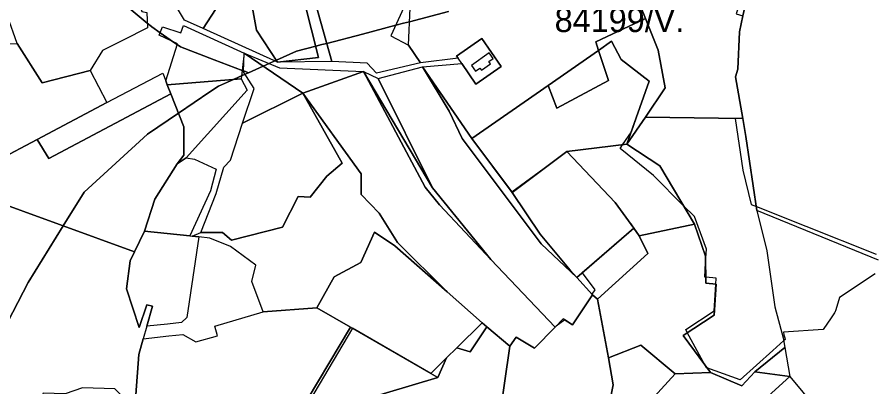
# Model space of a CAD drawing. Extents: x -477304 to -465429, y -1159113 to -1149210.
# Drawn here: x -473443 to -472912, y -1156987 to -1156758 of the extents above; entities that cross this region are included whole.
import ezdxf

# ---------------------------------------------------------------- set-up
doc = ezdxf.new("R2010")
doc.units = 0
for name, color, linetype in [('BPEJ_s', 7, 'Continuous'), ('PUPFL_s', 7, 'Continuous'), ('trav_porost_s', 7, 'Continuous')]:
    doc.layers.add(name, color=color, linetype=linetype)

msp = doc.modelspace()

# ---------------------------------------------------------------- linework, layer by layer
at = {"layer": 'BPEJ_s'}
for points in [[(-472896.74, -1156756.4), (-472922.42, -1156748.63), (-472938.96, -1156743.55), (-472959.42, -1156733.15), (-472984.05, -1156714.17), (-472993.88, -1156757.66), (-472996.14, -1156767.65), (-472997.03, -1156790.58), (-472998.5, -1156795.52), (-472994.04, -1156821.31), (-472998.71, -1156821.23), (-472993.88, -1156853.19), (-472988.81, -1156874.48), (-472985.62, -1156875.75), (-472955, -1156887.92), (-472911.44, -1156905.22)], [(-472896.74, -1156756.4), (-472922.42, -1156748.63), (-472938.96, -1156743.55), (-472959.42, -1156733.15), (-472984.05, -1156714.17), (-472993.88, -1156757.66), (-472996.14, -1156767.65), (-472997.03, -1156790.58), (-472998.5, -1156795.52), (-472994.04, -1156821.31), (-472998.71, -1156821.23), (-472993.88, -1156853.19), (-472988.81, -1156874.48), (-472985.62, -1156875.75), (-472955, -1156887.92), (-472911.44, -1156905.22)], [(-473388.37, -1156740.6), (-473362.48, -1156762.23), (-473359.93, -1156764.35), (-473359.71, -1156764.51), (-473354.43, -1156768.17), (-473346.17, -1156773.88), (-473344, -1156775.39), (-473341.91, -1156776.84), (-473320.98, -1156784.83), (-473303.71, -1156791.43), (-473303.29, -1156791.59), (-473302.81, -1156791.78), (-473301.24, -1156792.38), (-473299.89, -1156792.89), (-473301.94, -1156793.8), (-473304.11, -1156794.77), (-473305.53, -1156795.4), (-473309.19, -1156797.04), (-473318.32, -1156801.11), (-473323.69, -1156804.74), (-473343.17, -1156817.93), (-473362.36, -1156830.93), (-473401.55, -1156866.82), (-473414.49, -1156887.65), (-473436.23, -1156922.65), (-473451.98, -1156953.51)], [(-473176.15, -1156754.99), (-473200.18, -1156761.29), (-473204.02, -1156762.29), (-473208.72, -1156763.52), (-473229.4, -1156768.94), (-473251.36, -1156774.7), (-473254.47, -1156775.51), (-473258.27, -1156776.5), (-473270.12, -1156779.61), (-473282.61, -1156785.18), (-473283.51, -1156785.58), (-473287.03, -1156787.15), (-473290.69, -1156788.78), (-473299.89, -1156792.89), (-473301.24, -1156792.38), (-473302.81, -1156791.78), (-473303.29, -1156791.59), (-473303.71, -1156791.43), (-473320.98, -1156784.83), (-473341.91, -1156776.84), (-473344, -1156775.39), (-473346.17, -1156773.88), (-473354.43, -1156768.17), (-473359.71, -1156764.51), (-473359.93, -1156764.35), (-473362.48, -1156762.23), (-473388.37, -1156740.6)], [(-473436.23, -1156922.65), (-473414.49, -1156887.65), (-473401.55, -1156866.82), (-473362.36, -1156830.93), (-473343.17, -1156817.93), (-473323.69, -1156804.74), (-473318.32, -1156801.11), (-473309.19, -1156797.04), (-473305.53, -1156795.4), (-473304.11, -1156794.77), (-473301.94, -1156793.8), (-473299.89, -1156792.89), (-473290.69, -1156788.78), (-473287.03, -1156787.15), (-473283.51, -1156785.58), (-473282.61, -1156785.18), (-473270.12, -1156779.61), (-473258.27, -1156776.5), (-473254.47, -1156775.51), (-473251.36, -1156774.7), (-473229.4, -1156768.94), (-473208.72, -1156763.52), (-473204.02, -1156762.29), (-473200.18, -1156761.29), (-473176.15, -1156754.99)], [(-472912.11, -1156917.39), (-472934.08, -1156931.92), (-472936.54, -1156939.59), (-472937.12, -1156941.38), (-472937.21, -1156941.51), (-472939.26, -1156944.55), (-472944.21, -1156951.85), (-472968.88, -1156953.54), (-472968.52, -1156955.06), (-472968.09, -1156956.92), (-472967.86, -1156957.93), (-472968.69, -1156958.68), (-472975.44, -1156964.77), (-472995.57, -1156982.93), (-473016.18, -1156975.62), (-473016.51, -1156975.5), (-473017.23, -1156974.18), (-473028.33, -1156953.73), (-473029.35, -1156951.85), (-473011.78, -1156940.36), (-473010.67, -1156923.68), (-473010.43, -1156920.09), (-473016.91, -1156919.47), (-473017.53, -1156919.41), (-473017, -1156910.42), (-473016.51, -1156902.18), (-473023.95, -1156881.91), (-473030.85, -1156875), (-473049.29, -1156856.57), (-473069.9, -1156839.68), (-473068.43, -1156837.52), (-473062.92, -1156829.43), (-473051.89, -1156798.17), (-473069.33, -1156784.66), (-473075.2, -1156773.36), (-473083.23, -1156779.1), (-473114.45, -1156800.78), (-473161.74, -1156833.63), (-473136.95, -1156866.69), (-473106.08, -1156844.12), (-473102.82, -1156841.71), (-473072.97, -1156873.12), (-473064.02, -1156885.57), (-473062.76, -1156886.76), (-473063.01, -1156886.98), (-473061.5, -1156889.08), (-473093.44, -1156916.83), (-473085.64, -1156927.33), (-473087.43, -1156929.86), (-473087.03, -1156930.3), (-473099.42, -1156948.88), (-473104.11, -1156945.79), (-473109.57, -1156949.79), (-473110.14, -1156950.37), (-473122.86, -1156963.44), (-473134.26, -1156956.59), (-473138.18, -1156962.14), (-473152.33, -1156950.22), (-473155.23, -1156947.66), (-473170.96, -1156963.11), (-473177.42, -1156969.45), (-473187.12, -1156978.97), (-473235.59, -1156950.97), (-473268.15, -1157005.97)], [(-472912.11, -1156917.39), (-472934.08, -1156931.92), (-472936.54, -1156939.59), (-472937.12, -1156941.38), (-472937.21, -1156941.51), (-472939.26, -1156944.55), (-472944.21, -1156951.85), (-472968.88, -1156953.54), (-472968.52, -1156955.06), (-472968.09, -1156956.92), (-472967.86, -1156957.93), (-472968.69, -1156958.68), (-472975.44, -1156964.77), (-472995.57, -1156982.93), (-473016.18, -1156975.62), (-473016.51, -1156975.5), (-473017.23, -1156974.18), (-473028.33, -1156953.73), (-473029.35, -1156951.85), (-473011.78, -1156940.36), (-473010.67, -1156923.68), (-473010.43, -1156920.09), (-473016.91, -1156919.47), (-473017.53, -1156919.41), (-473017, -1156910.42), (-473016.51, -1156902.18), (-473023.95, -1156881.91), (-473030.85, -1156875), (-473049.29, -1156856.57), (-473069.9, -1156839.68), (-473068.43, -1156837.52), (-473062.92, -1156829.43), (-473051.89, -1156798.17), (-473069.33, -1156784.66), (-473075.2, -1156773.36), (-473083.23, -1156779.1), (-473114.45, -1156800.78), (-473161.74, -1156833.63), (-473136.95, -1156866.69), (-473106.08, -1156844.12), (-473102.82, -1156841.71), (-473072.97, -1156873.12), (-473064.02, -1156885.57), (-473062.76, -1156886.76), (-473063.01, -1156886.98), (-473061.5, -1156889.08), (-473093.44, -1156916.83), (-473085.64, -1156927.33), (-473087.43, -1156929.86), (-473087.03, -1156930.3), (-473099.42, -1156948.88), (-473104.11, -1156945.79), (-473109.57, -1156949.79), (-473110.14, -1156950.37), (-473122.86, -1156963.44), (-473134.26, -1156956.59), (-473138.18, -1156962.14), (-473152.33, -1156950.22), (-473155.23, -1156947.66), (-473170.96, -1156963.11), (-473177.42, -1156969.45), (-473187.12, -1156978.97), (-473235.59, -1156950.97), (-473268.15, -1157005.97)], [(-473451.98, -1156953.51), (-473436.23, -1156922.65)]]:
    msp.add_lwpolyline(points, dxfattribs=at)
at = {"layer": 'PUPFL_s'}
for points in [[(-472910.06, -1156908.96), (-472985.26, -1156878.14), (-472992.15, -1156832.26), (-472994.04, -1156821.31), (-472998.5, -1156795.52), (-472997.03, -1156790.58), (-472996.14, -1156767.65), (-472993.88, -1156757.66), (-472982.99, -1156709.48), (-472958.33, -1156729.74), (-472937.78, -1156740.97), (-472893.83, -1156755.76)], [(-473463.39, -1156869.81), (-473370.38, -1156903.75), (-473373.01, -1156909.3), (-473375.35, -1156926.64), (-473367.56, -1156950.62), (-473362.8, -1156936.46), (-473359.22, -1156937.3), (-473362.74, -1156949.76), (-473364.97, -1156957.67), (-473367.69, -1156967.32), (-473369.57, -1156992.27), (-473356.39, -1157002.65), (-473355.77, -1157014.32), (-473372.53, -1157014.45), (-473375.84, -1156995.2), (-473382.56, -1156988.47), (-473402.51, -1156987.86), (-473413.33, -1156991.54), (-473426.79, -1156991.26), (-473429.29, -1156999.54), (-473471.03, -1157013.97)]]:
    msp.add_lwpolyline(points, dxfattribs=at)
for points in [[(-473479.07, -1156859.72), (-473493.51, -1156831.55), (-473508.42, -1156813.61), (-473532.72, -1156812.53), (-473590.97, -1156823.09), (-473549.63, -1156807.91), (-473508.36, -1156792.73), (-473460.14, -1156775.02), (-473442.99, -1156774.8), (-473427.59, -1156799.07), (-473397.77, -1156791.4), (-473387.39, -1156811.39), (-473430.5, -1156834.12)], [(-473136.67, -1156867.07), (-473161.74, -1156833.63), (-473114.45, -1156800.78), (-473109.16, -1156814.74), (-473077.05, -1156797.73), (-473083.23, -1156779.1), (-473075.2, -1156773.36), (-473069.33, -1156784.66), (-473051.89, -1156798.17), (-473065.66, -1156837.18), (-473102.82, -1156841.71)], [(-473109.16, -1156814.74), (-473114.45, -1156800.78), (-473083.23, -1156779.1), (-473077.05, -1156797.73)], [(-473357.74, -1156871.05), (-473364.18, -1156890.97), (-473370.38, -1156903.75), (-473463.39, -1156869.81), (-473476.24, -1156865.24), (-473479.07, -1156859.72), (-473430.5, -1156834.12), (-473423.35, -1156845.98), (-473347.87, -1156805.93), (-473339.88, -1156826.32), (-473339.92, -1156843.97), (-473343.89, -1156849.27)], [(-473230.15, -1156868.16), (-473219.02, -1156879.87), (-473207.7, -1156898.03), (-473176.98, -1156928.43), (-473209.28, -1156900.03), (-473221.79, -1156891.57), (-473230.42, -1156910.33), (-473246.76, -1156919.16), (-473257.52, -1156938.31), (-473290.86, -1156940.92), (-473297.71, -1156922.03), (-473295.26, -1156912.05), (-473310.99, -1156900.45), (-473323.81, -1156895.2), (-473330.65, -1156894.49), (-473334.73, -1156894.07), (-473329.32, -1156891.71), (-473315.9, -1156891.77), (-473310.35, -1156896.6), (-473278.8, -1156888.37), (-473269.18, -1156869.53), (-473261.75, -1156869.93), (-473251.42, -1156856.99), (-473241.93, -1156848.93), (-473266.15, -1156805.46), (-473230.05, -1156855.52)], [(-472968.98, -1156956.91), (-472968.01, -1156962.95), (-472986.54, -1156978.04), (-472994.54, -1156986.71), (-473014.07, -1156978.5), (-473030.96, -1156955.43), (-473011.72, -1156943.02), (-473010.42, -1156923.7), (-473016.87, -1156923.16), (-473017.04, -1156906.49), (-473023.97, -1156886.6), (-473045.39, -1156850.53), (-473065.66, -1156837.18), (-473054.25, -1156820.33), (-472994.04, -1156821.31), (-472992.15, -1156832.26), (-472985.26, -1156878.14), (-472979.05, -1156903.13), (-472974.17, -1156937.69)], [(-473072.97, -1156873.12), (-473102.82, -1156841.71), (-473065.66, -1156837.18), (-473045.39, -1156850.53), (-473023.97, -1156886.6), (-473058.03, -1156893.92), (-473061.5, -1156889.08)], [(-473011.72, -1156943.02), (-473030.96, -1156955.43), (-473014.07, -1156978.5), (-473035.9, -1156979.35), (-473057.12, -1156961.5), (-473077.19, -1156969.28), (-473083.83, -1156933.1), (-473052.79, -1156904.76), (-473058.03, -1156893.92), (-473023.97, -1156886.6), (-473017.04, -1156906.49), (-473016.87, -1156923.16), (-473010.42, -1156923.7)], [(-473087.03, -1156930.3), (-473096.71, -1156919.67), (-473061.5, -1156889.08), (-473058.03, -1156893.92), (-473052.79, -1156904.76), (-473083.83, -1156933.1)], [(-473087.03, -1156930.3), (-473083.83, -1156933.1), (-473077.19, -1156969.28), (-473074.11, -1156986.06), (-473076.61, -1156998.53), (-473078.01, -1157005.55), (-473144.57, -1157006.56), (-473138.18, -1156962.14), (-473134.26, -1156956.59), (-473122.86, -1156963.44), (-473110.14, -1156950.37), (-473105.07, -1156945.16), (-473099.42, -1156948.88)], [(-473356.39, -1157002.65), (-473346.03, -1157006.89), (-473303.66, -1157002.44), (-473303.28, -1157007.09), (-473269.97, -1157006.03), (-473264.06, -1157005.84), (-473182.62, -1156981.57), (-473177.42, -1156969.45), (-473170.96, -1156963.11), (-473162.6, -1156965.55), (-473152.33, -1156950.22), (-473138.18, -1156962.14), (-473144.57, -1157006.56), (-473244.36, -1157010.73), (-473355.77, -1157014.32)], [(-473187.12, -1156978.97), (-473182.62, -1156981.57), (-473264.06, -1157005.84), (-473269.97, -1157006.03), (-473236.79, -1156950.28)], [(-473155.23, -1156947.66), (-473152.33, -1156950.22), (-473162.6, -1156965.55), (-473170.96, -1156963.11)], [(-473076.61, -1156998.53), (-473074.11, -1156986.06), (-473077.19, -1156969.28), (-473057.12, -1156961.5), (-473035.9, -1156979.35), (-473055.22, -1157000.48), (-473068.42, -1157002.16)], [(-472986.54, -1156978.04), (-472968.01, -1156962.95), (-472964.9, -1156980.85)], [(-473177.42, -1156969.45), (-473182.62, -1156981.57), (-473187.12, -1156978.97)], [(-472986.54, -1156978.04), (-472964.9, -1156980.85), (-472982.79, -1156997.22), (-473078.01, -1157005.55), (-473076.61, -1156998.53), (-473068.42, -1157002.16), (-473055.22, -1157000.48), (-473035.9, -1156979.35), (-473014.07, -1156978.5), (-472994.54, -1156986.71)], [(-472982.79, -1156997.22), (-472964.9, -1156980.85), (-472931.72, -1157020.89), (-472916.82, -1157050.73), (-472926.18, -1157059.46), (-472922.93, -1157063.61), (-472936.82, -1157054.62), (-472940.11, -1157059.72), (-472947.1, -1157049.52), (-472939.55, -1157050.53), (-472933.13, -1157044.69), (-472929.96, -1157028.34), (-472968.38, -1157009.83), (-472971.02, -1157014.61)]]:
    msp.add_lwpolyline(points, close=True, dxfattribs=at)
at = {"layer": 'trav_porost_s'}
for points in [[(-473054.25, -1156820.33), (-473042.03, -1156802.28), (-473046.32, -1156779), (-473054.16, -1156759.3), (-473063.12, -1156737.28), (-473061.25, -1156722.79), (-473054.49, -1156710.97), (-473021.31, -1156696.59), (-473009.86, -1156702.33), (-473017.75, -1156701.15), (-473018.23, -1156705.11), (-473003.08, -1156709.3), (-473002.62, -1156705.96), (-472984.74, -1156714.93), (-472998.04, -1156756.39), (-472993.88, -1156757.66), (-472996.14, -1156767.65), (-472997.03, -1156790.58), (-472998.5, -1156795.52), (-472994.04, -1156821.31)], [(-473203.75, -1156752.59), (-473211.69, -1156770.06), (-473200.83, -1156775.84), (-473193.47, -1156786.73), (-473220.69, -1156793.16), (-473226.39, -1156786.99), (-473248.19, -1156785.95), (-473261.93, -1156737.2), (-473249.2, -1156733.56), (-473257.42, -1156713.96), (-473227.05, -1156700.92), (-473214.92, -1156716.13), (-473214.17, -1156735.4), (-473221.76, -1156739.19), (-473218.39, -1156746.5), (-473208.13, -1156745.48)], [(-473100.46, -1156706.87), (-473093.84, -1156716.31), (-473074.97, -1156716.83), (-473056.66, -1156710.97), (-473054.49, -1156710.97), (-473061.25, -1156722.79), (-473063.12, -1156737.28), (-473054.16, -1156759.3), (-473085.01, -1156773.73), (-473083.23, -1156779.1), (-473114.45, -1156800.78), (-473161.74, -1156833.63), (-473192.15, -1156789.32), (-473167.91, -1156787.19), (-473159.16, -1156799.87), (-473143.52, -1156789.08), (-473155.48, -1156771.76), (-473171.11, -1156782.55), (-473170.21, -1156783.85), (-473193.47, -1156786.73), (-473200.83, -1156775.84), (-473199.79, -1156752.65), (-473145.28, -1156713.55)], [(-473296.71, -1156731.38), (-473258.82, -1156710.62), (-473257.42, -1156713.96), (-473249.2, -1156733.56), (-473261.93, -1156737.2), (-473248.19, -1156785.95), (-473281.86, -1156786.33), (-473256.48, -1156783.45), (-473265.29, -1156749.24), (-473297.81, -1156750.75), (-473294.8, -1156766.48), (-473281.86, -1156786.33), (-473327.92, -1156765.57), (-473307.22, -1156733.6), (-473303.13, -1156733.8), (-473296.71, -1156731.38), (-473296.04, -1156740.35), (-473290.55, -1156739.96), (-473290.38, -1156742.35), (-473279.7, -1156741.59), (-473280.14, -1156735.5), (-473282.73, -1156735.69), (-473283.11, -1156730.4)], [(-473367.9, -1156728.95), (-473368.26, -1156730.63), (-473370.39, -1156740.46), (-473365.78, -1156755.03), (-473362.66, -1156755.7), (-473362.4, -1156765.19), (-473377.31, -1156772.7), (-473390.19, -1156779.19), (-473397.77, -1156791.4), (-473427.59, -1156799.07), (-473442.99, -1156774.8), (-473448.91, -1156757.89), (-473458.08, -1156746.11), (-473416.75, -1156720.64), (-473410.73, -1156720.39)], [(-473307.22, -1156733.6), (-473327.92, -1156765.57), (-473339.34, -1156760.42), (-473347.19, -1156747.14), (-473345.27, -1156739.68), (-473351.15, -1156738.17), (-473352.51, -1156735.31), (-473343.62, -1156726.24), (-473337.31, -1156724.4), (-473332.83, -1156723.1), (-473322.1, -1156719.98), (-473315.32, -1156720.91), (-473315.28, -1156723.01), (-473310.09, -1156723.93), (-473311.18, -1156730.96), (-473311.55, -1156733.38)], [(-473297.81, -1156750.75), (-473265.29, -1156749.24), (-473256.48, -1156783.45), (-473281.86, -1156786.33), (-473294.8, -1156766.48)], [(-473054.25, -1156820.33), (-473065.66, -1156837.18), (-473051.89, -1156798.17), (-473069.33, -1156784.66), (-473075.2, -1156773.36), (-473083.23, -1156779.1), (-473085.01, -1156773.73), (-473054.16, -1156759.3), (-473046.32, -1156779), (-473042.03, -1156802.28)], [(-473355.02, -1156769.67), (-473353, -1156764.52), (-473341.61, -1156768.18), (-473340.12, -1156763.57), (-473302.46, -1156780.79), (-473304.33, -1156796.65), (-473350.08, -1156800.3), (-473351.02, -1156797.9), (-473343.87, -1156774.98)], [(-473170.21, -1156783.85), (-473171.11, -1156782.55), (-473155.48, -1156771.76), (-473143.52, -1156789.08), (-473159.16, -1156799.87), (-473167.91, -1156787.19)], [(-473302.83, -1156792.39), (-473302.46, -1156780.79), (-473266.15, -1156805.46), (-473303.45, -1156824.07), (-473296.34, -1156802.69)], [(-473228.65, -1156792.08), (-473266.15, -1156805.46), (-473302.46, -1156780.79), (-473280.73, -1156789.75)], [(-473148.54, -1156784.06), (-473150.99, -1156780.65), (-473161.83, -1156788.44), (-473159.34, -1156791.94), (-473156.64, -1156790.01), (-473155.71, -1156791.31), (-473150.19, -1156787.34), (-473151.18, -1156785.96)], [(-473228.65, -1156792.08), (-473190.47, -1156863.76), (-473181.7, -1156874.73), (-473149.96, -1156908.54), (-473110.14, -1156950.37), (-473122.86, -1156963.44), (-473134.26, -1156956.59), (-473138.18, -1156962.14), (-473152.33, -1156950.22), (-473155.23, -1156947.66), (-473176.98, -1156928.43), (-473207.7, -1156898.03), (-473219.02, -1156879.87), (-473230.15, -1156868.16), (-473230.05, -1156855.52), (-473266.15, -1156805.46)], [(-473185.92, -1156864.16), (-473228.65, -1156792.08), (-473219.51, -1156796.5)], [(-473228.65, -1156792.08), (-473185.92, -1156864.16), (-473149.96, -1156908.54), (-473181.7, -1156874.73), (-473190.47, -1156863.76)], [(-473105.07, -1156945.16), (-473110.14, -1156950.37), (-473149.96, -1156908.54), (-473185.92, -1156864.16), (-473219.51, -1156796.5), (-473192.15, -1156789.32), (-473175.73, -1156816.59), (-473167.66, -1156833.67), (-473118.86, -1156898.75), (-473096.71, -1156919.67), (-473087.03, -1156930.3), (-473099.42, -1156948.88)], [(-473119.44, -1156892.84), (-473100.91, -1156915.16), (-473096.71, -1156919.67), (-473118.86, -1156898.75), (-473167.66, -1156833.67), (-473175.73, -1156816.59), (-473192.15, -1156789.32), (-473161.74, -1156833.63), (-473136.67, -1156867.07)], [(-473347.87, -1156805.93), (-473423.35, -1156845.98), (-473430.5, -1156834.12), (-473387.39, -1156811.39), (-473352.87, -1156793.19), (-473351.02, -1156797.9), (-473350.08, -1156800.3)], [(-473350.08, -1156800.3), (-473304.33, -1156796.65), (-473300.65, -1156803.6), (-473338.48, -1156845.56), (-473343.89, -1156849.27), (-473339.92, -1156843.97), (-473339.88, -1156826.32), (-473347.87, -1156805.93)], [(-473241.93, -1156848.93), (-473251.42, -1156856.99), (-473261.75, -1156869.93), (-473269.18, -1156869.53), (-473278.8, -1156888.37), (-473310.35, -1156896.6), (-473315.9, -1156891.77), (-473329.32, -1156891.71), (-473319.85, -1156867.61), (-473315.14, -1156851.38), (-473311.07, -1156846.96), (-473303.45, -1156824.07), (-473266.15, -1156805.46)], [(-473096.71, -1156919.67), (-473100.91, -1156915.16), (-473119.44, -1156892.84), (-473136.67, -1156867.07), (-473102.82, -1156841.71), (-473072.97, -1156873.12), (-473061.5, -1156889.08)], [(-473323.39, -1156865.96), (-473336.19, -1156893.92), (-473364.18, -1156890.97), (-473357.74, -1156871.05), (-473343.89, -1156849.27), (-473338.48, -1156845.56), (-473333.17, -1156846.33), (-473319.84, -1156852.55)], [(-473375.35, -1156926.64), (-473373.01, -1156909.3), (-473370.38, -1156903.75), (-473364.18, -1156890.97), (-473336.19, -1156893.92), (-473334.73, -1156894.07), (-473330.65, -1156894.49), (-473337.99, -1156944.31), (-473341.31, -1156947.58), (-473349.87, -1156948.46), (-473362.74, -1156949.76), (-473359.22, -1156937.3), (-473362.8, -1156936.46), (-473367.56, -1156950.62)], [(-473177.42, -1156969.45), (-473187.12, -1156978.97), (-473236.79, -1156950.28), (-473257.52, -1156938.31), (-473246.76, -1156919.16), (-473230.42, -1156910.33), (-473221.79, -1156891.57), (-473209.28, -1156900.03), (-473176.98, -1156928.43), (-473155.23, -1156947.66), (-473170.96, -1156963.11)], [(-473303.66, -1157002.44), (-473346.03, -1157006.89), (-473356.39, -1157002.65), (-473369.57, -1156992.27), (-473367.69, -1156967.32), (-473364.97, -1156957.67), (-473349.12, -1156955.79), (-473340.56, -1156954.91), (-473332.42, -1156959.39), (-473319.1, -1156955.8), (-473320.71, -1156949.82), (-473290.86, -1156940.92), (-473257.52, -1156938.31), (-473236.79, -1156950.28), (-473269.97, -1157006.03), (-473303.28, -1157007.09)]]:
    msp.add_lwpolyline(points, close=True, dxfattribs=at)

# ---------------------------------------------------------------- texts
at = {"layer": 'BPEJ_s'}
msp.add_text('84199/V.', height=15, dxfattribs=at).set_placement((-473110.42, -1156767.71))

doc.saveas('drawing.dxf')
